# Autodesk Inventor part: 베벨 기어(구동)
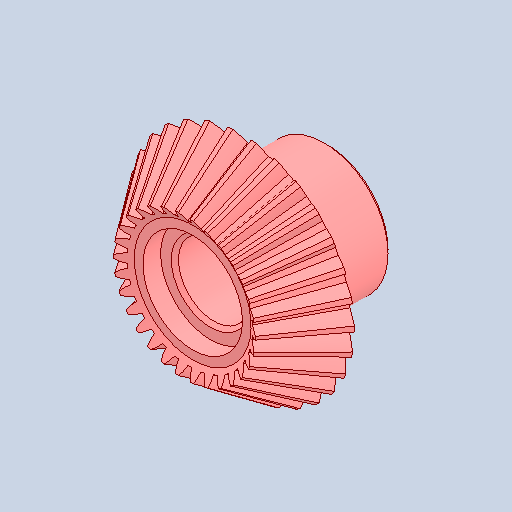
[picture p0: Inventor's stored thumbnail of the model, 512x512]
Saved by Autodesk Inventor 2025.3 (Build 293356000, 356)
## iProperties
Created: 2026-01
Part Number: 베벨 기어(구동)
Material: 강철, 합금
Document SubType Name: Modeling
Designer: PC-13
Density: 7.73 g/cm^3
Appearance: 기본값
Author: jhkim
Sending System: Autodesk Inventor 2026
Preprocessor: ST-DEVELOPER v20.1
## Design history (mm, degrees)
feature "Solid1"
node "솔리드1"
